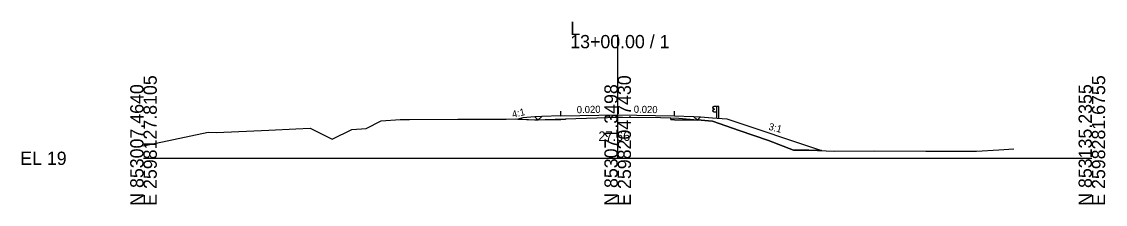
# Model space of a CAD drawing. Extents: x -26 to 1203, y -10 to 9526.
# Drawn here: x -25.7 to 202.8, y 2990.3 to 3028.8 of the extents above; entities that cross this region are included whole.
import ezdxf

# ---------------------------------------------------------------- set-up
doc = ezdxf.new("R2010")
doc.units = 0
for name, color, linetype in [('Exist Cross Section Cell', 7, 'Continuous'), ('Exist XS Center Line Elevation Label', 7, 'Continuous'), ('Exist XS Ground Line', 7, 'Continuous'), ('Prop XS Earthwork Shape', 7, 'Continuous'), ('Prop XS EOT Tick Mark', 7, 'Continuous'), ('Prop XS Finish Grade', 7, 'Continuous'), ('Prop XS Finish Grade Earthwork', 7, 'Continuous'), ('Prop XS Finish Grade Paved Shoulder', 7, 'Continuous'), ('Prop XS Finish Grade Pavement', 7, 'Continuous'), ('Prop XS Guardrail', 7, 'Continuous'), ('Prop XS Pvmt Edge Slope', 7, 'Continuous'), ('Prop XS SE Text', 7, 'Continuous'), ('Prop XS Side Slope Text', 7, 'Continuous'), ('Prop XS Subgrade Earthwork', 7, 'Continuous')]:
    doc.layers.add(name, color=color, linetype=linetype)

msp = doc.modelspace()

# ---------------------------------------------------------------- linework, layer by layer
at = {"layer": 'Exist Cross Section Cell'}
for p, q in [((100, 3000), (100, 3025.98)), ((0, 3000), (100, 3000)), ((100, 3000), (200, 3000))]:
    msp.add_line(p, q, dxfattribs=at)
at = {"layer": 'Exist XS Ground Line'}
for p, q in [((46.94, 3006.31), (50.11, 3007.9)), ((50.11, 3007.9), (54.11, 3008.16)), ((54.11, 3008.16), (56.11, 3008.17)), ((56.11, 3008.17), (66.3, 3008.21)), ((66.3, 3008.21), (76.51, 3008.27)), ((76.51, 3008.27), (78.51, 3008.28)), ((78.51, 3008.28), (82.51, 3008.07)), ((82.51, 3008.07), (89.02, 3008.31)), ((89.02, 3008.31), (100.04, 3008.66)), ((100.04, 3008.66), (101.05, 3008.65)), ((101.05, 3008.65), (109.05, 3008.59)), ((109.05, 3008.59), (111.19, 3008.56)), ((111.19, 3008.56), (112.93, 3008.44)), ((112.93, 3008.44), (119.17, 3007.88)), ((119.17, 3007.88), (119.98, 3007.8)), ((119.98, 3007.8), (125.64, 3005.89)), ((2.69, 3003.22), (13.66, 3005.51)), ((13.66, 3005.51), (15.37, 3005.41)), ((15.37, 3005.41), (26.45, 3005.94)), ((26.45, 3005.94), (32.12, 3006.18)), ((32.12, 3006.18), (35.18, 3006.32)), ((35.18, 3006.32), (39.81, 3004)), ((39.81, 3004), (43.94, 3006.06)), ((43.94, 3006.06), (46.94, 3006.31)), ((125.64, 3005.89), (131.81, 3003.78)), ((0, 3002.63), (2.69, 3003.22)), ((131.81, 3003.78), (137.1, 3001.72)), ((137.1, 3001.72), (140.33, 3001.73)), ((140.33, 3001.73), (145.8, 3001.51)), ((145.8, 3001.51), (154.14, 3001.55)), ((154.14, 3001.55), (164.99, 3001.51)), ((164.99, 3001.51), (175.64, 3001.5)), ((175.64, 3001.5), (180.41, 3001.76)), ((180.41, 3001.76), (183.57, 3002))]:
    msp.add_line(p, q, dxfattribs=at)
at = {"layer": 'Prop XS Earthwork Shape'}
for points in [[(82.5, 3008.73), (80, 3008.52), (78.94, 3008.26), (82.51, 3008.07), (83.14, 3008.09)], [(89.02, 3008.15), (88, 3008.13), (83.19, 3008.04), (83.14, 3008.09), (89.02, 3008.31)], [(111.19, 3008.15), (111.19, 3008.55), (112.93, 3008.44), (116.86, 3008.09), (116.81, 3008.04), (112, 3008.13)], [(117.5, 3008.73), (120, 3008.52), (123, 3008.28), (142.98, 3001.63), (140.33, 3001.73), (137.1, 3001.72), (131.81, 3003.78), (125.64, 3005.89), (119.98, 3007.8), (119.17, 3007.88), (116.86, 3008.09)]]:
    msp.add_lwpolyline(points, close=True, dxfattribs=at)
at = {"layer": 'Prop XS EOT Tick Mark'}
for p, q in [((88, 3008.92), (88, 3009.92)), ((112, 3008.92), (112, 3009.92))]:
    msp.add_line(p, q, dxfattribs=at)
at = {"layer": 'Prop XS Finish Grade'}
for p, q in [((84, 3008.84), (82.5, 3008.73)), ((116, 3008.84), (117.5, 3008.73))]:
    msp.add_line(p, q, dxfattribs=at)
at = {"layer": 'Prop XS Finish Grade Earthwork'}
for p, q in [((80, 3008.52), (78.94, 3008.26)), ((82.5, 3008.73), (80, 3008.52)), ((117.5, 3008.73), (120, 3008.52)), ((120, 3008.52), (123, 3008.28)), ((123, 3008.28), (142.98, 3001.63))]:
    msp.add_line(p, q, dxfattribs=at)
at = {"layer": 'Prop XS Finish Grade Paved Shoulder'}
for p, q in [((88, 3008.92), (84, 3008.84)), ((112, 3008.92), (116, 3008.84))]:
    msp.add_line(p, q, dxfattribs=at)
at = {"layer": 'Prop XS Finish Grade Pavement'}
for p, q in [((88, 3008.92), (100, 3009.16)), ((100, 3009.16), (112, 3008.92))]:
    msp.add_line(p, q, dxfattribs=at)
at = {"layer": 'Prop XS Guardrail'}
for p, q in [((120.03, 3010.72), (120, 3010.66)), ((120, 3010.66), (120.03, 3010.6)), ((120.03, 3010.1), (120, 3010.04)), ((120, 3010.04), (120.03, 3009.98)), ((120.32, 3010.92), (120.03, 3010.72)), ((120.03, 3010.6), (120.32, 3010.4)), ((120.32, 3010.3), (120.03, 3010.1)), ((120.03, 3009.98), (120.32, 3009.78)), ((120.82, 3010.92), (120.32, 3010.92)), ((120.32, 3010.4), (120.32, 3010.3)), ((120.32, 3009.78), (120.82, 3009.78)), ((121.32, 3010.92), (120.82, 3010.92)), ((120.82, 3010.92), (120.82, 3008.42)), ((121.32, 3008.42), (121.32, 3010.92))]:
    msp.add_line(p, q, dxfattribs=at)
at = {"layer": 'Prop XS Pvmt Edge Slope'}
for p, q in [((84, 3008.84), (83.19, 3008.04)), ((116, 3008.84), (116.81, 3008.04))]:
    msp.add_line(p, q, dxfattribs=at)
at = {"layer": 'Prop XS Subgrade Earthwork'}
for p, q in [((83.19, 3008.04), (82.5, 3008.73)), ((88, 3008.13), (83.19, 3008.04)), ((89.02, 3008.15), (88, 3008.13)), ((89.02, 3008.15), (89.02, 3008.31)), ((111.19, 3008.15), (111.19, 3008.55)), ((111.19, 3008.15), (112, 3008.13)), ((112, 3008.13), (116.81, 3008.04)), ((116.81, 3008.04), (117.5, 3008.73))]:
    msp.add_line(p, q, dxfattribs=at)

# ---------------------------------------------------------------- texts
at = {"layer": 'Exist Cross Section Cell'}
for s, p in [('L', (90, 3025.98)), ('13+00.00 / 1', (90, 3023.18)), ('EL 19', (-26, 2998.6))]:
    msp.add_text(s, height=2.8, dxfattribs=at).set_placement(p)
for s, p in [('E 2598127.8105', (2.8, 2990)), ('E 2598204.7430', (102.8, 2990)), ('E 2598281.6755', (202.8, 2990)), ('N 853007.4640', (0, 2990)), ('N 853071.3498', (100, 2990)), ('N 853135.2355', (200, 2990))]:
    msp.add_text(s, height=2.8, rotation=90, dxfattribs=at).set_placement(p)
at = {"layer": 'Exist XS Center Line Elevation Label'}
msp.add_text('27.66', height=2, dxfattribs=at).set_placement((95.94, 3003.66))
at = {"layer": 'Prop XS SE Text'}
for rotation, p in [(1.1458, (91.38, 3009.49)), (358.8542, (103.38, 3009.6))]:
    msp.add_text('0.020', height=1.5, rotation=rotation, dxfattribs=at).set_placement(p)
at = {"layer": 'Prop XS Side Slope Text'}
for s, rotation, p in [('4:1', 13.2903, (77.88, 3008.49)), ('3:1', 345.9638, (131.71, 3006.03))]:
    msp.add_text(s, height=1.5, rotation=rotation, dxfattribs=at).set_placement(p)

doc.saveas('drawing.dxf')
